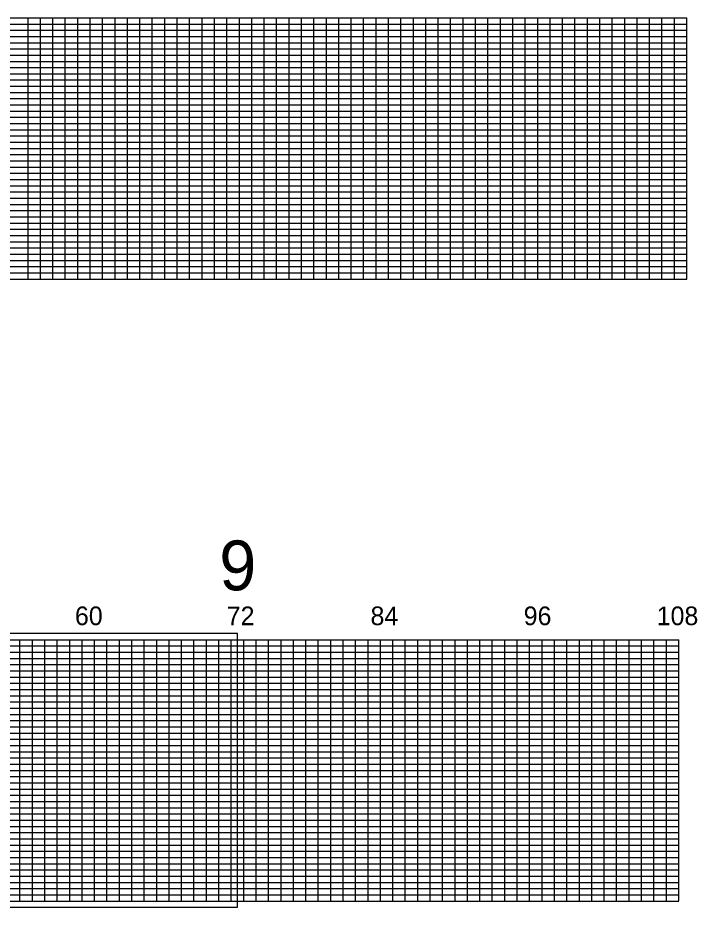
# Model space of a CAD drawing. Extents: x 1914168 to 1925341, y 720939 to 777401.
# Drawn here: x 1917165 to 1919898, y 755939 to 759514 of the extents above; entities that cross this region are included whole.
import ezdxf

# ---------------------------------------------------------------- set-up
doc = ezdxf.new("R2010")
doc.units = 0
for name, color, linetype in [('RD_PD_ALT1_CL', 7, 'Continuous'), ('RD_PD_WallFill', 7, 'Continuous'), ('RD_SHT_IplotShp', 7, 'Continuous')]:
    doc.layers.add(name, color=color, linetype=linetype)

msp = doc.modelspace()

# ---------------------------------------------------------------- linework, layer by layer
at = {"layer": 'RD_PD_WallFill'}
for p, q in [((1914506.4, 759514.1), (1919856.4, 759514.2)), ((1917206.4, 758464.2), (1917206.4, 759514.2)), ((1917256.4, 758464.2), (1917256.4, 759514.2)), ((1917306.4, 758464.2), (1917306.4, 759514.2)), ((1917356.4, 758464.2), (1917356.4, 759514.2)), ((1917406.4, 758464.2), (1917406.4, 759514.2)), ((1917456.4, 758464.2), (1917456.4, 759514.2)), ((1917506.4, 758464.2), (1917506.4, 759514.2)), ((1917556.4, 758464.2), (1917556.4, 759514.2)), ((1917606.4, 758464.1), (1917606.4, 759514.2)), ((1917656.4, 758464.2), (1917656.4, 759514.2)), ((1917706.4, 758464.2), (1917706.4, 759514.2)), ((1917756.4, 758464.2), (1917756.4, 759514.2)), ((1917806.4, 758464.2), (1917806.4, 759514.2)), ((1917856.4, 758464.2), (1917856.4, 759514.2)), ((1917906.4, 758464.1), (1917906.4, 759514.2)), ((1917956.4, 758464.1), (1917956.4, 759514.2)), ((1918006.4, 758464.2), (1918006.4, 759514.2)), ((1918056.4, 758464.2), (1918056.4, 759514.2)), ((1918106.4, 758464.2), (1918106.4, 759514.2)), ((1918156.4, 758464.2), (1918156.4, 759514.2)), ((1918206.4, 758464.2), (1918206.4, 759514.2)), ((1918256.4, 758464.2), (1918256.4, 759514.2)), ((1918306.4, 758464.2), (1918306.4, 759514.2)), ((1918356.4, 758464.2), (1918356.4, 759514.2)), ((1918406.4, 758464.2), (1918406.4, 759514.2)), ((1918456.4, 758464.2), (1918456.4, 759514.2)), ((1918506.4, 758464.2), (1918506.4, 759514.2)), ((1918556.4, 758464.2), (1918556.4, 759514.2)), ((1918606.4, 758464.2), (1918606.4, 759514.2)), ((1918656.4, 758464.2), (1918656.4, 759514.2)), ((1918706.4, 758464.2), (1918706.4, 759514.2)), ((1918756.4, 758464.2), (1918756.4, 759514.2)), ((1918806.4, 758464.2), (1918806.4, 759514.2)), ((1918856.4, 758464.2), (1918856.4, 759514.2)), ((1918906.4, 758464.2), (1918906.4, 759514.2)), ((1918956.4, 758464.2), (1918956.4, 759514.2)), ((1919006.4, 758464.2), (1919006.4, 759514.2)), ((1919056.4, 758464.2), (1919056.4, 759514.2)), ((1919106.4, 758464.2), (1919106.4, 759514.2)), ((1919156.4, 758464.2), (1919156.4, 759514.2)), ((1919206.4, 758464.2), (1919206.4, 759514.2)), ((1919256.4, 758464.2), (1919256.4, 759514.2)), ((1919306.4, 758464.2), (1919306.4, 759514.2)), ((1919356.4, 758464.2), (1919356.4, 759514.2)), ((1919406.4, 758464.2), (1919406.4, 759514.2)), ((1919456.4, 758464.2), (1919456.4, 759514.2)), ((1919506.4, 758464.2), (1919506.4, 759514.2)), ((1919556.4, 758464.2), (1919556.4, 759514.2)), ((1919606.4, 758464.2), (1919606.4, 759514.2)), ((1919656.4, 758464.2), (1919656.4, 759514.2)), ((1919706.4, 758464.2), (1919706.4, 759514.2)), ((1919756.4, 758464.2), (1919756.4, 759514.2)), ((1919806.4, 758464.2), (1919806.4, 759514.2)), ((1919856.4, 758464.2), (1919856.4, 759514.2)), ((1914956.4, 759489.1), (1919856.4, 759489.1)), ((1914956.4, 759464.1), (1919856.4, 759464.1)), ((1914956.4, 759439.1), (1919856.4, 759439.1)), ((1914956.4, 759414.2), (1919856.4, 759414.1)), ((1914956.4, 759389.1), (1919856.4, 759389.2)), ((1914506.4, 759364.1), (1919856.4, 759364.1)), ((1914506.4, 759339.1), (1919856.4, 759339.1)), ((1914506.4, 759314.1), (1919856.4, 759314.2)), ((1914506.4, 759289.2), (1919856.4, 759289.1)), ((1914506.4, 759264.2), (1919856.4, 759264.2)), ((1914506.4, 759239.1), (1919856.4, 759239.1)), ((1914506.4, 759214.1), (1919856.4, 759214.1)), ((1914506.4, 759189.2), (1919856.4, 759189.1)), ((1914506.4, 759164.1), (1919856.4, 759164.1)), ((1914506.4, 759139.2), (1919856.4, 759139.1)), ((1914506.4, 759114.1), (1919856.4, 759114.1)), ((1914506.4, 759089.1), (1919856.4, 759089.2)), ((1914506.4, 759064.1), (1919856.4, 759064.1)), ((1914506.4, 759039.1), (1919856.4, 759039.2)), ((1914506.4, 759014.1), (1919856.4, 759014.1)), ((1914506.4, 758989.1), (1919856.4, 758989.1)), ((1914506.4, 758964.2), (1919856.4, 758964.1)), ((1914506.4, 758939.1), (1919856.4, 758939.1)), ((1914506.4, 758914.1), (1919856.4, 758914.1)), ((1914506.4, 758889.1), (1919856.4, 758889.1)), ((1914506.4, 758864.1), (1919856.4, 758864.2)), ((1914506.4, 758839.1), (1919856.4, 758839.1)), ((1914506.4, 758814.1), (1919856.4, 758814.1)), ((1914506.4, 758789.1), (1919856.4, 758789.1)), ((1914506.4, 758764.1), (1919856.4, 758764.1)), ((1914506.4, 758739.1), (1919856.4, 758739.1)), ((1914506.4, 758714.1), (1919856.4, 758714.1)), ((1914506.4, 758689.1), (1919856.4, 758689.1)), ((1914506.4, 758664.1), (1919856.4, 758664.1)), ((1914506.4, 758639.1), (1919856.4, 758639.1)), ((1914506.4, 758614.1), (1919856.4, 758614.1)), ((1914506.4, 758589.1), (1919856.4, 758589.1)), ((1914506.4, 758564.1), (1919856.4, 758564.1)), ((1914506.4, 758539.1), (1919856.4, 758539.1)), ((1914506.4, 758514.1), (1919856.4, 758514.1)), ((1914556.4, 758489.1), (1919856.4, 758489.1)), ((1914506.4, 758464.1), (1919856.4, 758464.1)), ((1914474, 757014.1), (1919824, 757014.2)), ((1917174, 755964.2), (1917174, 757014.2)), ((1917224, 755964.2), (1917224, 757014.2)), ((1917274, 755964.2), (1917274, 757014.2)), ((1917324, 755964.2), (1917324, 757014.2)), ((1917374, 755964.2), (1917374, 757014.2)), ((1917424, 755964.2), (1917424, 757014.2)), ((1917474, 755964.2), (1917474, 757014.2)), ((1917524, 755964.2), (1917524, 757014.2)), ((1917574, 755964.1), (1917574, 757014.2)), ((1917624, 755964.2), (1917624, 757014.2)), ((1917674, 755964.2), (1917674, 757014.2)), ((1917724, 755964.2), (1917724, 757014.2)), ((1917774, 755964.2), (1917774, 757014.2)), ((1917824, 755964.2), (1917824, 757014.2)), ((1917874, 755964.1), (1917874, 757014.2)), ((1917924, 755964.1), (1917924, 757014.2)), ((1917974, 755964.2), (1917974, 757014.2)), ((1918024, 755964.2), (1918024, 757014.2)), ((1918074, 755964.2), (1918074, 757014.2)), ((1918124, 755964.2), (1918124, 757014.2)), ((1918174, 755964.2), (1918174, 757014.2)), ((1918224, 755964.2), (1918224, 757014.2)), ((1918274, 755964.2), (1918274, 757014.2)), ((1918324, 755964.2), (1918324, 757014.2)), ((1918374, 755964.2), (1918374, 757014.2)), ((1918424, 755964.2), (1918424, 757014.2)), ((1918474, 755964.2), (1918474, 757014.2)), ((1918524, 755964.2), (1918524, 757014.2)), ((1918574, 755964.2), (1918574, 757014.2)), ((1918624, 755964.2), (1918624, 757014.2)), ((1918674, 755964.2), (1918674, 757014.2)), ((1918724, 755964.2), (1918724, 757014.2)), ((1918774, 755964.2), (1918774, 757014.2)), ((1918824, 755964.2), (1918824, 757014.2)), ((1918874, 755964.2), (1918874, 757014.2)), ((1918924, 755964.2), (1918924, 757014.2)), ((1918974, 755964.2), (1918974, 757014.2)), ((1919024, 755964.2), (1919024, 757014.2)), ((1919074, 755964.2), (1919074, 757014.2)), ((1919124, 755964.2), (1919124, 757014.2)), ((1919174, 755964.2), (1919174, 757014.2)), ((1919224, 755964.2), (1919224, 757014.2)), ((1919274, 755964.2), (1919274, 757014.2)), ((1919324, 755964.2), (1919324, 757014.2)), ((1919374, 755964.2), (1919374, 757014.2)), ((1919424, 755964.2), (1919424, 757014.2)), ((1919474, 755964.2), (1919474, 757014.2)), ((1919524, 755964.2), (1919524, 757014.2)), ((1919574, 755964.2), (1919574, 757014.2)), ((1919624, 755964.2), (1919624, 757014.2)), ((1919674, 755964.2), (1919674, 757014.2)), ((1919724, 755964.2), (1919724, 757014.2)), ((1919774, 755964.2), (1919774, 757014.2)), ((1919824, 755964.2), (1919824, 757014.2)), ((1914924, 756989.1), (1919824, 756989.1)), ((1914924, 756964.1), (1919824, 756964.1)), ((1914924, 756939.1), (1919824, 756939.1)), ((1914924, 756914.2), (1919824, 756914.1)), ((1914924, 756889.1), (1919824, 756889.2)), ((1914474, 756864.1), (1919824, 756864.1)), ((1914474, 756839.1), (1919824, 756839.1)), ((1914474, 756814.1), (1919824, 756814.2)), ((1914474, 756789.2), (1919824, 756789.1)), ((1914474, 756764.2), (1919824, 756764.2)), ((1914474, 756739.1), (1919824, 756739.1)), ((1914474, 756714.1), (1919824, 756714.1)), ((1914474, 756689.2), (1919824, 756689.1)), ((1914474, 756664.1), (1919824, 756664.1)), ((1914474, 756639.2), (1919824, 756639.1)), ((1914474, 756614.1), (1919824, 756614.1)), ((1914474, 756589.1), (1919824, 756589.2)), ((1914474, 756564.1), (1919824, 756564.1)), ((1914474, 756539.1), (1919824, 756539.2)), ((1914474, 756514.1), (1919824, 756514.1)), ((1914474, 756489.1), (1919824, 756489.1)), ((1914474, 756464.2), (1919824, 756464.1)), ((1914474, 756439.1), (1919824, 756439.1)), ((1914474, 756414.1), (1919824, 756414.1)), ((1914474, 756389.1), (1919824, 756389.1)), ((1914474, 756364.1), (1919824, 756364.2)), ((1914474, 756339.1), (1919824, 756339.1)), ((1914474, 756314.1), (1919824, 756314.1)), ((1914474, 756289.1), (1919824, 756289.1)), ((1914474, 756264.1), (1919824, 756264.1)), ((1914474, 756239.1), (1919824, 756239.1)), ((1914474, 756214.1), (1919824, 756214.1)), ((1914474, 756189.1), (1919824, 756189.1)), ((1914474, 756164.1), (1919824, 756164.1)), ((1914474, 756139.1), (1919824, 756139.1)), ((1914474, 756114.1), (1919824, 756114.1)), ((1914474, 756089.1), (1919824, 756089.1)), ((1914474, 756064.1), (1919824, 756064.1)), ((1914474, 756039.1), (1919824, 756039.1)), ((1914474, 756014.1), (1919824, 756014.1)), ((1914524, 755989.1), (1919824, 755989.1)), ((1914474, 755964.1), (1919824, 755964.1))]:
    msp.add_line(p, q, dxfattribs=at)
at = {"layer": 'RD_SHT_IplotShp'}
msp.add_lwpolyline([(1914449, 755939.1), (1918049, 755939.1), (1918049, 757039.1), (1914449, 757039.1)], close=True, dxfattribs=at)

# ---------------------------------------------------------------- texts
at = {"layer": 'RD_PD_ALT1_CL'}
msp.add_text('9', height=200, dxfattribs=at).set_placement((1917975.8, 757213))
at = {"layer": 'RD_PD_WallFill'}
for s, p in [('60', (1917395.2, 757072.8)), ('72', (1918005.8, 757072.8)), ('84', (1918584.1, 757072.8)), ('96', (1919200.2, 757072.8)), ('108', (1919735.2, 757072.8))]:
    msp.add_text(s, height=75, dxfattribs=at).set_placement(p)

doc.saveas('drawing.dxf')
